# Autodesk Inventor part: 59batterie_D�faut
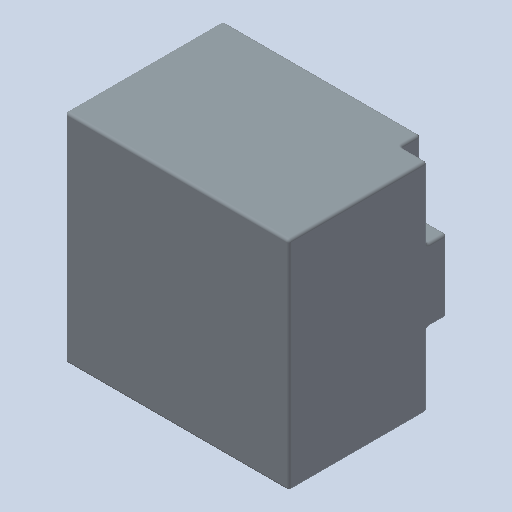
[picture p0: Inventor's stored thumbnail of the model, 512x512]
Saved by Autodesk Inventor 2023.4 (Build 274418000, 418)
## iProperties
Created: 2011-01
Part Number: 59batterie_D�faut
Document SubType Name: Modeling
Designer: eric
Density: 1 g/cm^3
Mass: 3330.52 g
Surface Area: 1352.2 cm^2
Volume: 3330.52 cm^3
Material: Générique
Appearance: Gris-bleu (clair)
Author: eric
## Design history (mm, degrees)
feature "Base1"
node "Corps solides"
node "Corps surfaciques"
node "Solide1"
